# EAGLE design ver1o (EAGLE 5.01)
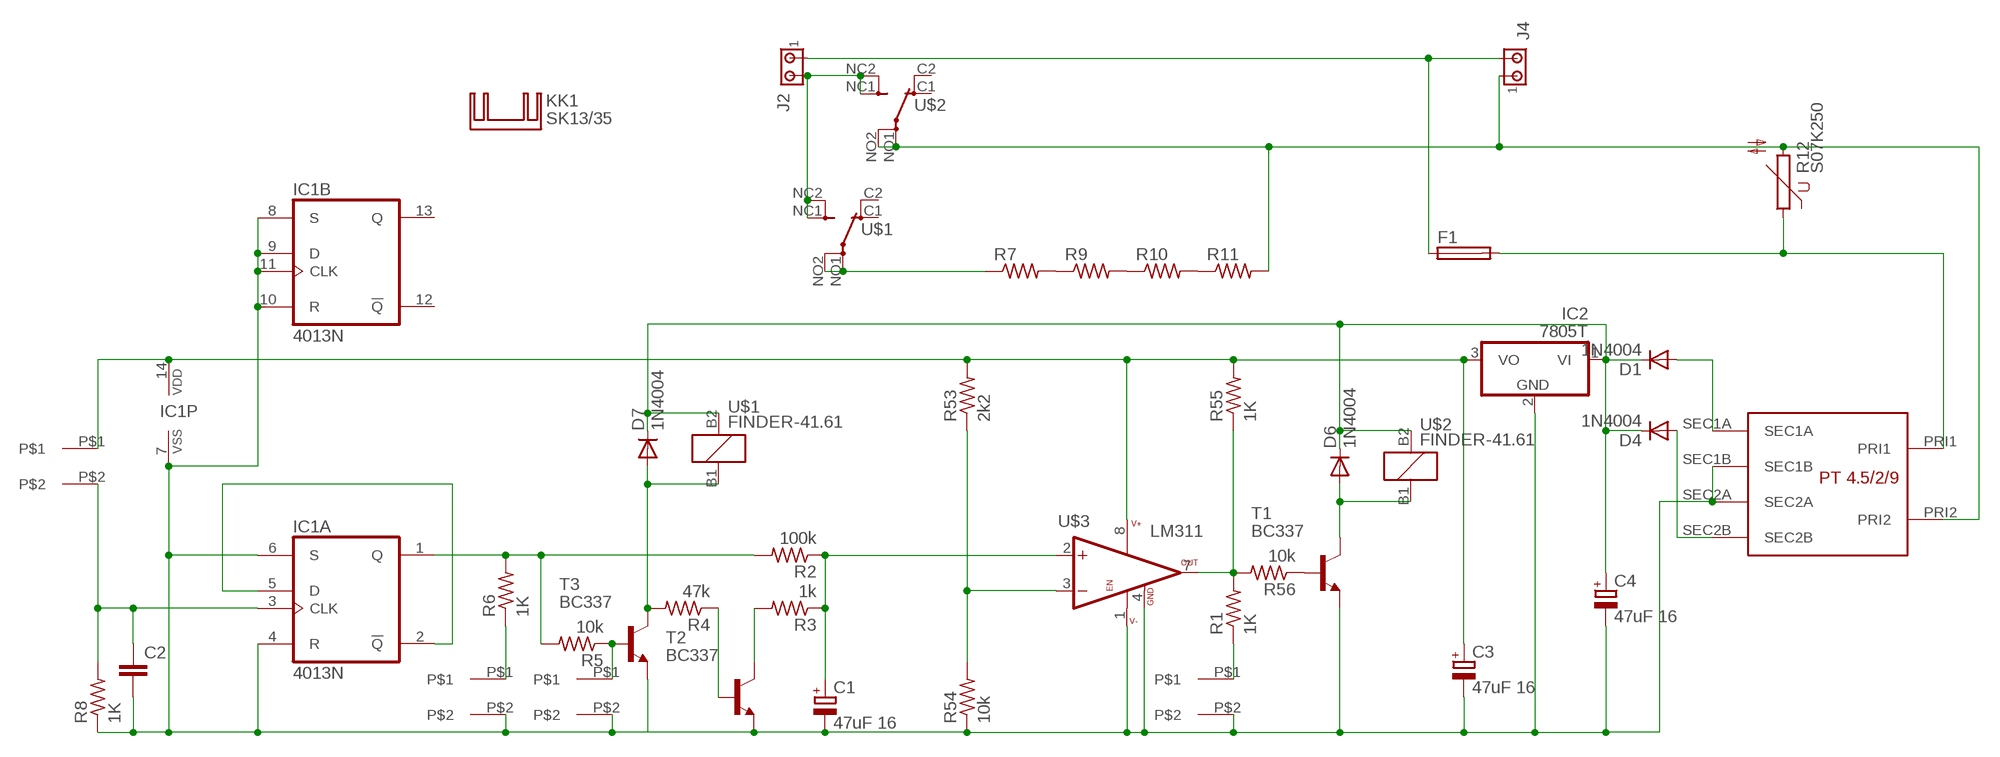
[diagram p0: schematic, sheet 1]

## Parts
C1  47uF 16  CPOL-EUE3.5-10  [E3,5-10]
C2  C-EU050-055X075  [C050-055X075]
C3  47uF 16  CPOL-EUE3.5-10  [E3,5-10]
C4  47uF 16  CPOL-EUE3.5-10  [E3,5-10]
D1  1N4004  [DO41-10]
D4  1N4004  [DO41-10]
D6  1N4004  [DO41-10]
D7  1N4004  [DO41-10]
F1  SH22,5A  [SH22,5A]
IC1  4013N  [DIL14]
IC2  7805T  [TO220H]
J2  MTA02-156  [1X2MTA]
J4  MTA02-156  [1X2MTA]
KK1  SK13/35  [SK13/35]
PULSANTE  PINS  [PINS]
R1  1K  R-US_0207/12  [0207/12]
R2  100k  R-US_0207/12  [0207/12]
R3  1k  R-US_0207/12  [0207/12]
R4  47k  R-US_0207/12  [0207/12]
R5  10k  R-US_0207/12  [0207/12]
R6  1K  R-US_0207/12  [0207/12]
R7  R-US_0922V  [0922V]
R8  1K  R-US_0207/12  [0207/12]
R9  R-US_0922V  [0922V]
R10  R-US_0922V  [0922V]
R11  R-US_0922V  [0922V]
R12  S07K250  [S07K250]
R53  2k2  R-US_0207/12  [0207/12]
R54  10k  R-US_0207/12  [0207/12]
R55  1K  R-US_0207/12  [0207/12]
R56  10k  R-US_0207/12  [0207/12]
T1  BC337  [TO92]
T2  BC337  [TO92]
T3  BC337  [TO92]
U$1  FINDER-41.61  [FINDER-41.61]
U$2  FINDER-41.61  [FINDER-41.61]
U$3  LM311  [DIL08]
U$4  TRANSF_PCB_4.5W  [PCB_TRANSF_4W]
U$7  PINS  [PINS]
U$10  PINS  [PINS]
U$11  PINS  [PINS]

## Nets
+V: C3.+ IC1.14(P:VDD) IC2.3(VO) PULSANTE.P$1 R53.2 R55.2 U$3.8(V+)
GND: C1.- C2.2 C3.- C4.- IC1.4(A:R) IC1.6(A:S) IC1.7(P:VSS) IC1.8(B:S) IC1.9(B:D) IC1.10(B:R) IC1.11(B:CLK) IC2.2(GND) R8.1 R54.1 T1.1(E) T2.1(E) T3.1(E) U$3.1(V-) U$3.4(GND) U$4.SEC1B U$4.SEC2A U$7.P$2 U$10.P$2 U$11.P$2
N$1: R6.1 U$10.P$1
N$2: IC1.1(A:Q) R2.2 R5.2 R6.2
N$3: D6.A T1.3(C) U$2.B1
N$4: C1.+ R2.1 R3.1 U$3.2(+IN)
N$5: R3.2 T2.3(C)
N$6: D7.A R4.2 T3.3(C) U$1.B1
N$7: R4.1 T2.2(B)
N$8: R5.1 T3.2(B) U$7.P$1
N$9: IC1.2(A:!Q) IC1.5(A:D)
N$10: C2.1 IC1.3(A:CLK) PULSANTE.P$2 R8.2
N$11: F1.2 R12.1 U$4.PRI1
N$12: D4.A U$4.SEC2B
N$13: D1.A U$4.SEC1A
N$16: F1.1 J2.1 J4.2
N$17: J2.2 U$1.NC1(S) U$1.NC2(S) U$2.NC1(S) U$2.NC2(S)
N$18: J4.1 R11.2 R12.2 U$2.NO1(P) U$2.NO2(P) U$4.PRI2
N$19: R7.1 U$1.NO1(P) U$1.NO2(P)
N$20: R7.2 R9.1
N$21: R9.2 R10.1
N$22: R10.2 R11.1
N$23: R1.1 U$11.P$1
N$24: R53.1 R54.2 U$3.3(-IN)
N$25: C4.+ D1.C D4.C D6.C D7.C IC2.1(VI) U$1.B2 U$2.B2
N$43: R1.2 R55.1 R56.2 U$3.7(!OUT)
N$44: R56.1 T1.2(B)
Unconnected: IC1.12(B:!Q) IC1.13(B:Q) U$1.C1(O) U$1.C2(O) U$2.C1(O) U$2.C2(O)

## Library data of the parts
C1 C3 C4 = rcl:CPOL-EU: POLARIZED CAPACITOR, European symbol
C2 = rcl:C-EU: CAPACITOR, European symbol
D1 D4 D6 D7 = diode:1N4004: DIODE
F1 = fuse:SH22,5A: FUSE HOLDER
IC1 = 40xx:4013: Dual D FLIP FLOP, set/reset
IC2 = linear:78*: Positive VOLTAGE REGULATOR Source: http://cache.national.com/ds/LM/LM78L05.pdf http://www.fairchildsemi.com/ds/LM/LM7805.pdf
J2 J4 = con-amp:MTA02-156: AMP connector
KK1 = heatsink:SK13/35: HEATSINK
PULSANTE U$7 U$10 U$11 = varie:PINS
R1-R11 R53-R56 = rcl:R-US_: RESISTOR, American symbol
R12 = varistor:S07K250: VARISTOR
T1-T3 = transistor-neu-to92:BC337: NPN TRANSISTOR
U$1 U$2 = relay:FINDER-41.61
U$3 = LM311:LM311
U$4 = mylib:TRANSF_PCB_4.5W

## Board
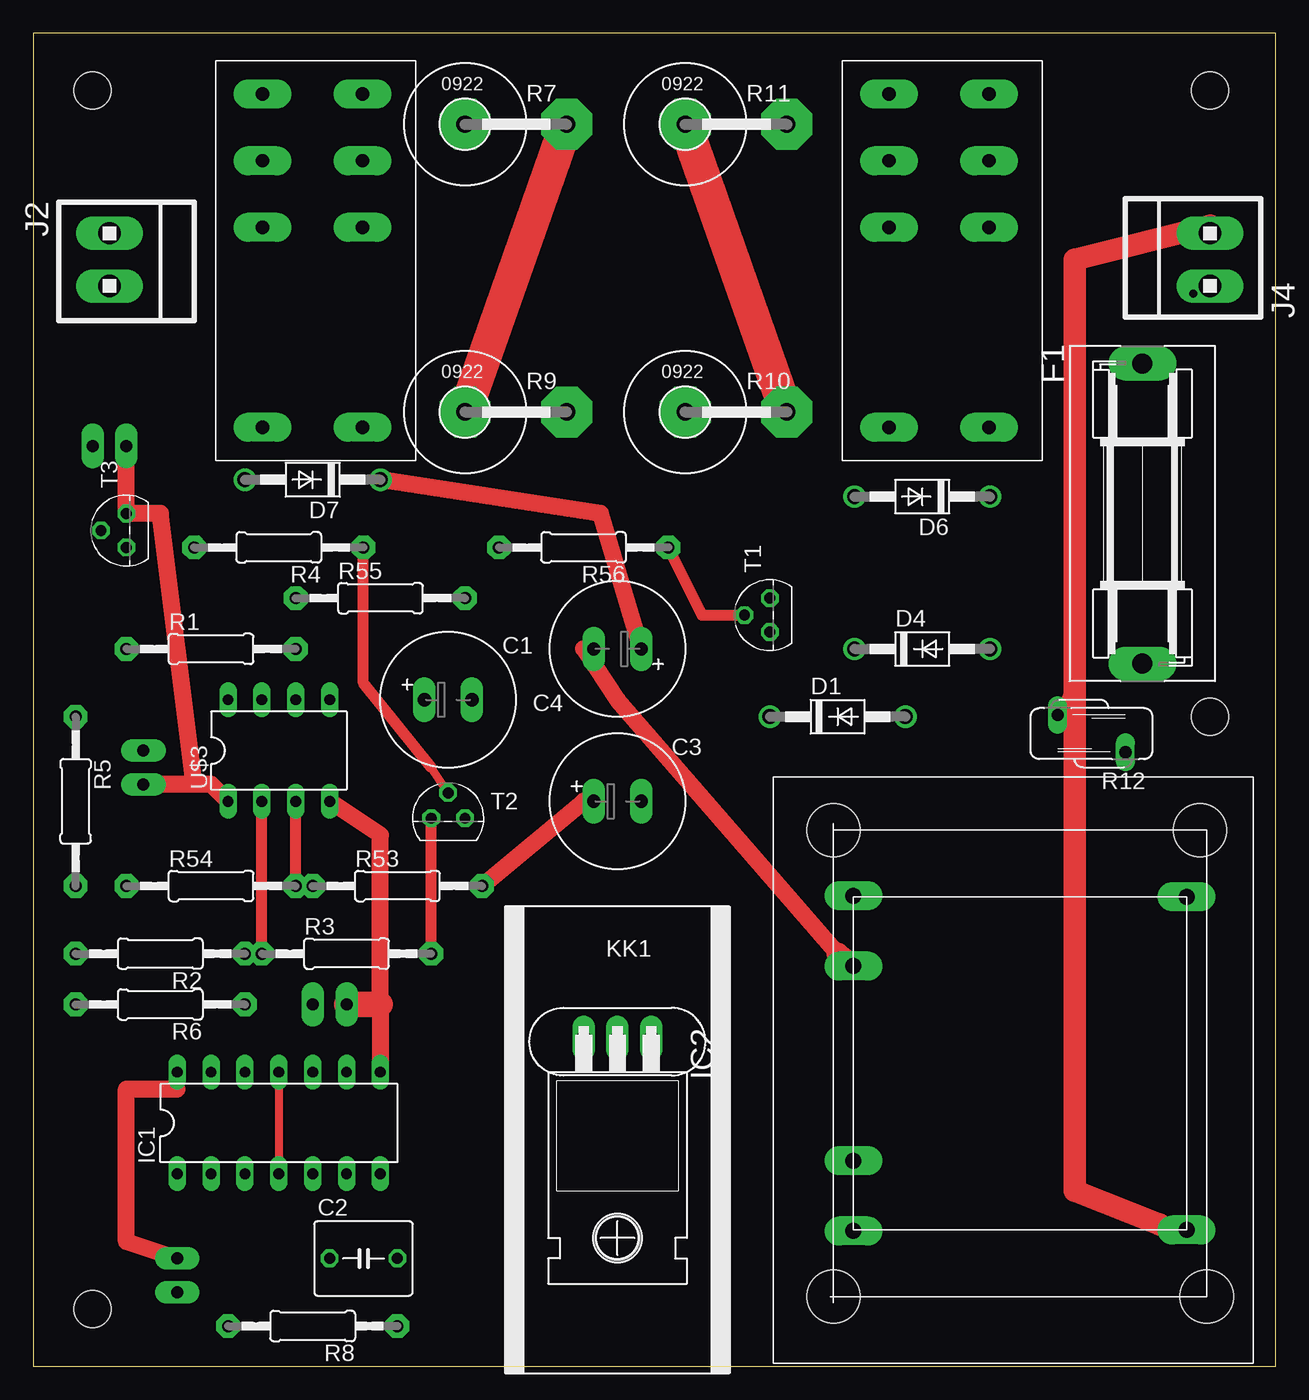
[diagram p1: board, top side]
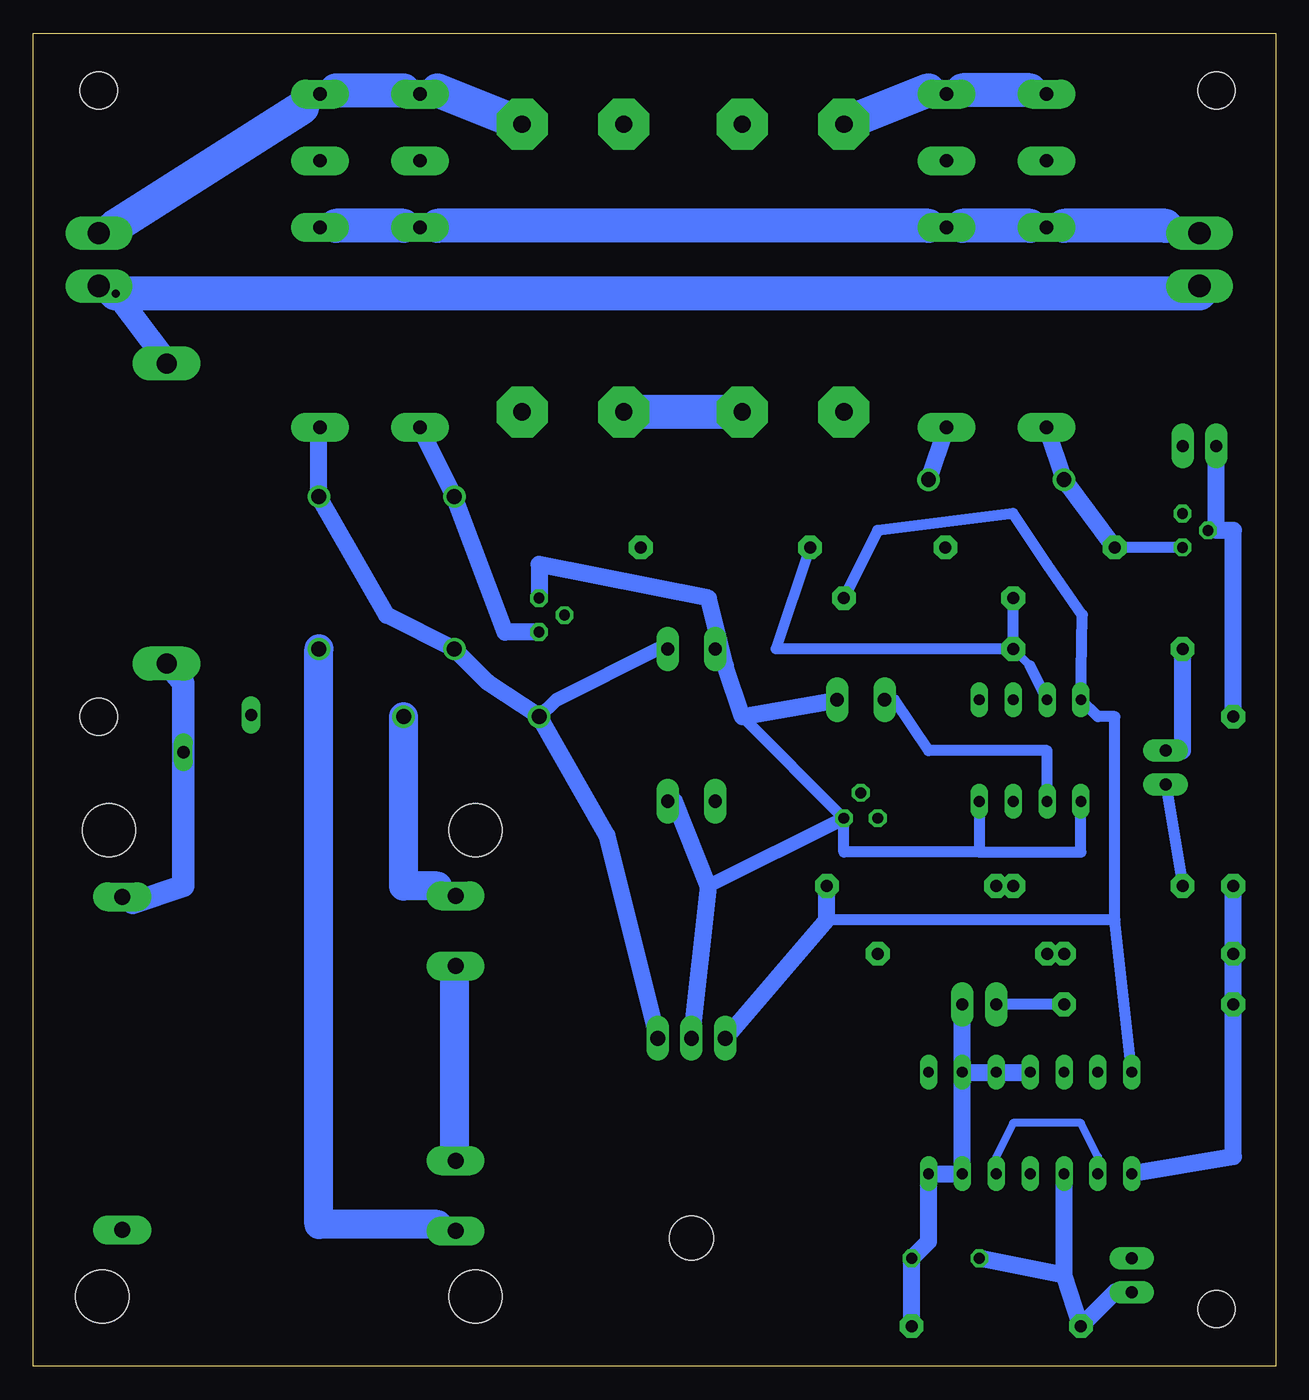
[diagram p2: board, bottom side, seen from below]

Size 93.17 x 100 mm. Coordinates in mm from the lower left corner, seen from the top.
Outline: 0,0 93.17,0 93.17,100 0,100 0,0
Copper layers (1*16): Top 0.035mm / dielectric 1.5mm / Bottom 0.035mm
Design rules "default": minimum track width 10mil, minimum drill 24mil, track to track 8mil, track to pad 8mil, pad to pad 8mil, via to via 8mil, smd to smd 8mil, copper to edge 40mil, drill to drill 8mil, minimum pad ring 10mil, minimum via ring 8mil, stop-mask expansion 4mil, vias tented up to drill 0mil, thermal gap 10mil
Holes 2.8 mm at 88.26,48.73 4.44,4.28 4.44,95.72 88.26,95.72

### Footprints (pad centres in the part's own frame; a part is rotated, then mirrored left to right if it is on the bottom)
E3,5-10 = drill 1 pad 1.676 long: + -1.778,0; - 1.778,0
C050-055X075 = drill 0.813 octagon: 1 -2.54,0; 2 2.54,0
DO41-10 = drill 1.118 round: A 5.08,0; C -5.08,0
SH22,5A = drill 1.5 pad 2.54 long: 1 -11.252,0; 2 11.252,0
DIL14 = drill 0.813 long: 1 -7.62,-3.81; 2 -5.08,-3.81; 3 -2.54,-3.81; 4 0,-3.81; 5 2.54,-3.81; 6 5.08,-3.81; 7 7.62,-3.81; 8 7.62,3.81; 9 5.08,3.81; 10 2.54,3.81; 11 0,3.81; 12 -2.54,3.81; 13 -5.08,3.81; 14 -7.62,3.81
TO220H = drill 1.118 long: 1 -2.54,-10.16; 2 0,-10.16; 3 2.54,-10.16 | hole 3.302: 0,4.826
1X2MTA = drill 1.676 long: 1 1.981,0; 2 -1.981,0
PINS = drill 0.9 pad 1.676 long: P$1 -2.54,0; P$2 0,0
0207/12 = drill 0.9 pad 1.778 octagon: 1 -6.35,0; 2 6.35,0
0922V = drill 1.3 pad 3.81 octagon: 1 -5.08,0; 2 2.54,0
S07K250 = drill 0.914 long: 1 -1.397,-2.54; 2 1.397,2.54
TO92 = drill 0.813 octagon: 1 1.27,0; 2 0,1.905; 3 -1.27,0
FINDER-41.61 = drill 1 pad 2.184 long: B1 -7.5,2.5; B2 -7.5,-5; C1 12.5,2.5; C2 12.5,-5; NC1 7.5,2.5; NC2 7.5,-5; NO1 17.5,2.5; NO2 17.5,-5
DIL08 = drill 0.813 long: 1 -3.81,-3.81; 2 -1.27,-3.81; 3 1.27,-3.81; 4 3.81,-3.81; 5 3.81,3.81; 6 1.27,3.81; 7 -1.27,3.81; 8 -3.81,3.81
PCB_TRANSF_4W = drill 1.2 pad 2.184 long: PRI1 13,-13; PRI2 -12,-13; SEC1A 13.08,12; SEC1B 7.81,12; SEC2A -6.81,12; SEC2B -12.08,12 | hole 4: -17,13.5; -17,-14.5; 18,-14; 18,13.5

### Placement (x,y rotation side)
C1  31.11,50 0 top
C2  24.76,8.09 0 top
C3  43.81,42.38 0 top
C4  43.81,53.81 180 top
D1  60.32,48.73 0 top
D4  66.67,53.81 0 top
D6  66.67,65.24 180 top
D7  20.95,66.51 180 top
F1  83.18,63.97 270 top
IC1  18.41,18.25 0 top
IC2  43.81,14.44 180 top
J2  5.71,83.02 270 top
J4  88.26,83.02 90 top
KK1  43.81,20.79 90 top
PULSANTE  10.79,5.55 270 top
R1  13.33,53.81 0 top
R2  9.52,30.95 180 top
R3  23.49,30.95 0 top
R4  18.41,61.43 180 top
R5  3.17,42.38 270 top
R6  9.52,27.14 180 top
R7  37.46,93.18 0 top
R8  20.95,3.01 180 top
R9  37.46,71.59 0 top
R10  53.97,71.59 0 top
R11  53.97,93.18 0 top
R12  79.37,47.46 90 top
R53  27.3,36.03 0 top
R54  13.33,36.03 0 top
R55  26.03,57.62 0 top
R56  41.27,61.43 180 top
T1  55.24,56.35 90 top
T2  31.11,41.11 0 top
T3  6.98,62.7 90 top
U$1  19.68,77.94 90 top
U$2  66.67,77.94 90 top
U$3  18.41,46.19 0 top
U$4  73.5,22.22 90 top
U$7  6.98,69.05 0 top
U$10  23.49,27.14 0 top
U$11  8.25,43.65 270 top

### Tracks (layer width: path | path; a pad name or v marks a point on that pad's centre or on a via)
+V
  Top 0.254: 41.27,42.38 C3.+
  Top 0.61: 10.79,20.79 IC1.14
  Top 1.27: R53.2 41.27,42.38 | 10.79,20.79 6.98,20.79 6.98,9.36 PULSANTE.P$1
  Bottom 0.254: 14.5,56.36 14.6,56.35
  Bottom 0.813: R55.2 29.84,62.7 19.68,63.97 17.14,60.16 14.5,56.36 U$3.8 13.33,48.73 12.06,48.73 12.06,33.49 | IC1.14 12.06,33.49 | 12.06,33.49 33.65,33.49
  Bottom 1.27: IC2.3 33.65,33.49 R53.2
GND
  Top 0.254: C4.- 41.27,53.81
  Top 0.61: IC1.11 IC1.4
  Top 1.27: 60.32,30.95 43.81,50 41.27,53.81 | 12.06,43.65 13.33,43.65 U$3.1 | 12.06,43.65 U$11.P$2 | 12.06,43.65 9.52,63.97 T3.1 U$7.P$2 | U$3.4 26.03,39.84 26.03,27.14 IC1.8
  Top 1.676: 60.32,30.95 U$4.SEC1B
  Top 1.93: U$10.P$2 26.03,27.14
  Bottom 0.254: 61.59,15.71 U$4.SEC2A | U$4.SEC1B 61.59,29.68 | 45.08,42.38 C3.- | 41.27,52.54 C4.-
  Bottom 0.813: 40,48.73 T2.1 32.38,38.57 22.22,38.57 | U$11.P$2 R54.1 | 22.22,38.57 14.6,38.57 U$3.1 | U$3.4 22.22,38.57
  Bottom 1.016: T2.1 42.54,36.03
  Bottom 1.27: T1.1 55.24,60.16 42.54,57.62 41.27,52.54 40,48.73 C1.- | 45.08,42.38 42.54,36.03 IC2.2 | R8.1 C2.2 26.03,9.36 IC1.7 IC1.6 IC1.9 | IC1.11 IC1.10 IC1.9 | IC1.9 U$10.P$2
  Bottom 2.184: 61.59,29.68 61.59,15.71
N$1
  Bottom 0.813: R6.1 U$10.P$1
N$2
  Bottom 1.27: R5.2 R2.2 R6.2 3.17,15.71 IC1.1
N$3
  Bottom 0.254: 64.13,70.32 U$2.B1
  Bottom 1.27: T1.3 57.78,55.08 D6.A 64.13,70.32
N$4
  Top 0.254: R3.1 R2.1
  Top 0.813: R3.1 U$3.2
  Bottom 0.254: 28.57,50 C1.+
  Bottom 0.813: 28.57,50 26.03,46.19 17.14,46.19 U$3.2
N$5
  Top 0.813: R3.2 T2.3
N$6
  Bottom 0.61: 17.14,70.32 U$1.B1
  Bottom 0.813: T3.3 R4.2
  Bottom 1.27: R4.2 D7.A 17.14,70.32
N$7
  Top 0.61: T2.2 29.84,44.92
  Top 0.813: 29.84,44.92 24.76,51.27 R4.1
N$8
  Bottom 0.254: 4.44,62.7 T3.2
  Bottom 1.27: R5.1 3.17,62.7 4.44,62.7 U$7.P$1
N$9
  Bottom 0.254: IC1.2 13.33,15.71 | 20.95,15.71 IC1.5
  Bottom 0.61: 13.33,15.71 14.6,18.25 19.68,18.25 20.95,15.71
N$10
  Bottom 0.254: PULSANTE.P$2 12.06,5.55
  Bottom 1.27: 12.06,5.55 R8.2 15.87,6.82 | 15.87,6.82 C2.1 | 15.87,6.82 IC1.3
N$11
  Bottom 0.254: U$4.PRI1 85.72,34.76
  Bottom 1.676: F1.2 81.91,51.27 R12.1 81.91,36.03 85.72,34.76
N$12
  Bottom 0.254: U$4.SEC2B 62.86,10.63
  Bottom 2.184: D4.A 71.75,10.63 62.86,10.63
N$13
  Bottom 1.27: U$4.SEC1A 62.86,36.03
  Bottom 2.184: D1.A 65.4,36.03 62.86,36.03
N$16  (via drill 0.6)
  Top 0.254: v86.99,80.48 J4.2
  Bottom 0.254: J2.1 5.71,80.48 | 83.18,75.4 F1.1
  Bottom 1.676: 83.18,75.4 v86.99,80.48 J4.2
  Bottom 2.54: 5.71,80.48 v86.99,80.48
N$17
  Bottom 0.254: 65.4,85.56 U$2.NC1 62.86,85.56 | 70.48,85.56 U$2.NC2 | 18.41,85.56 U$1.NC1 15.87,85.56 | 23.49,85.56 U$1.NC2 26.03,85.56 | 8.25,85.56 6.98,84.29 J2.2
  Bottom 2.54: 65.4,85.56 70.48,85.56 | 18.41,85.56 23.49,85.56 | 8.25,85.56 15.87,85.56 | 26.03,85.56 62.86,85.56
N$18
  Top 0.254: 84.45,10.63 U$4.PRI2 | 88.26,85.56 J4.1 | 78.1,52.54 R12.2
  Top 1.676: 84.45,10.63 78.1,13.17 78.1,52.54 78.1,83.02 88.26,85.56
  Bottom 0.254: 65.4,95.72 U$2.NO1 62.86,95.72 | 70.48,95.72 U$2.NO2 73.02,94.45 | J4.1 86.99,85.56
  Bottom 2.54: 70.48,95.72 65.4,95.72 | 62.86,95.72 R11.2 | 86.99,85.56 73.02,94.45
N$19
  Bottom 0.254: U$1.NO1 18.41,95.72 | 23.49,95.72 U$1.NO2 26.03,95.72
  Bottom 2.54: 18.41,95.72 23.49,95.72 | 26.03,95.72 R7.1
N$20
  Top 2.54: R9.1 R7.2
N$21
  Bottom 2.54: R9.2 R10.1
N$22
  Top 2.54: R10.2 R11.1
N$23
  Bottom 0.61: 6.98,46.19 U$11.P$1
  Bottom 1.27: 6.98,46.19 R1.1
N$24
  Top 0.254: R54.2 R53.1
  Top 0.813: R54.2 U$3.3
N$25
  Top 1.27: D7.C 42.54,63.97 C4.+
  Bottom 0.254: 71.75,70.32 U$2.B2 | 46.35,53.81 C4.+
  Bottom 1.016: 46.35,53.81 53.97,50 D1.C
  Bottom 1.27: 71.75,70.32 D6.C 66.67,56.35 D4.C 59.05,51.27 D1.C 50.16,39.84 IC2.1 | D7.C U$1.B2
N$43
  Bottom 0.61: 18.41,52.54 R1.2
  Bottom 0.813: U$3.7 18.41,52.54 | R55.1 R1.2 37.46,53.81 R56.2
N$44
  Top 0.813: R56.1 50.16,56.35 T1.2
